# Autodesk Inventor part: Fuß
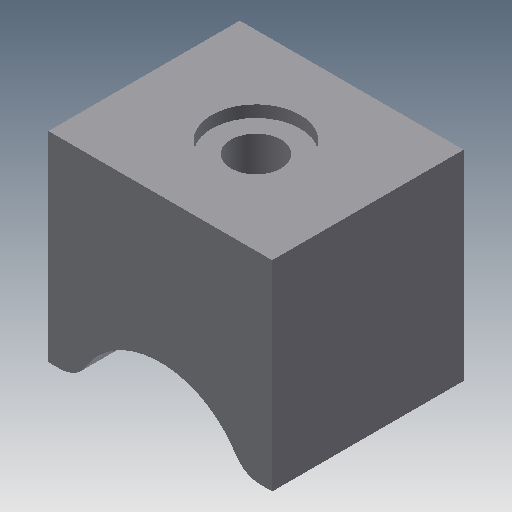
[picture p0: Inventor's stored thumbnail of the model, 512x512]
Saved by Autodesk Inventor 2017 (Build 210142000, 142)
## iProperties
Created: 2015-04
Part Number: Fuß
Material: Generisch
Document SubType Name: Modeling
Designer: e_krauts
Density: 1 g/cm^3
Appearance: Vorgabe
Mass: 34.0103 g
Surface Area: 76.7953 cm^2
Volume: 34.0103 cm^3
Author: e_krauts
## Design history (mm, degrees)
sketch "Skizze1"
  geometry: L1 (-19, 16.25)-(19, 16.25); L2 (19, 16.25)-(19, -16.25); L3 (19, -16.25)-(-19, -16.25); L4 (-19, -16.25)-(-19, 16.25); L5 (-19, 16.25)-(19, -16.25); L6 (19, 16.25)-(-19, -16.25); 1 further point
  constraints: 12 end point, 2 midpoint, 2 parallel, 1 horizontal, 1 perpendicular
  dimensions: "d0" = 38 distance of L2.end L3.end; "d1" = 32.5 distance of L1.end L2.end
extrude "Extrusion1" new body sketch "Skizze1" distance "d2" = 34; taper "d3" = 0 deg
sketch "Skizze2"
  geometry: L1 (0, 0)-(38, 0) reference; L2 (0, 34)-(38, 34) reference; L3 (0, 0)-(0, 34) reference; L4 (19, 34)-(19, 0); L5 (5.045, 34)-(32.955, 34); A1 r 15 centre (19, 39.5) between (5.045, 34) and (32.955, 34); 1 further point
  constraints: 4 end point, 3 point on line, 2 midpoint, 2 point on circle, 1 centre point, 1 parallel, 1 perpendicular
  dimensions: "d4" = 30 diameter of A1; "d5" = 39.5 distance from line of L1 A1.centre
extrude "Extrusion2" cut sketch "Skizze2" stored distance "d6" = 34; taper "d7" = 0 deg
fillet "Rundung1" dims "d8" = 5
sketch "Skizze3"
  geometry: 2 further points
  constraints: 1 coincident
hole "Bohrung1" sketch "Skizze3" at (0, 0) diameter "d9" = 8.5; stored, may be unused: countersink angle "d13" = 90 deg, drill point angle "d15" = 118 deg; dims "d10" = 6, "d11" = 15, "d12" = 2, "d14" = 8
node "Volumenkörper1"
